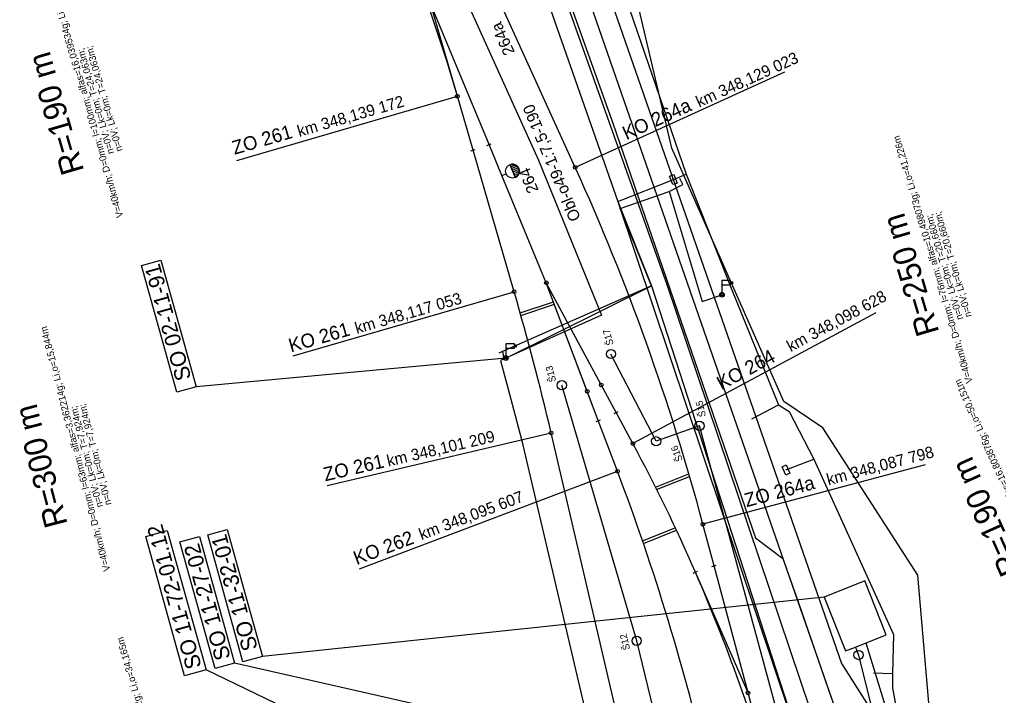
# Model space of a CAD drawing. Extents: x -820988 to -820703, y -1070846 to -1070074.
# Drawn here: x -820878.5 to -820772.1, y -1070418.8 to -1070345.4 of the extents above; entities that cross this region are included whole.
import ezdxf

# ---------------------------------------------------------------- set-up
doc = ezdxf.new("R2010")
doc.units = 0
for name, color, linetype in [('_PS_SO_číslo', 7, 'Continuous'), ('PS-11-02-31', 7, 'Continuous'), ('PS-11-02-41', 7, 'Continuous'), ('PS-11-02-91', 7, 'Continuous'), ('PS-11-02-92', 7, 'Continuous'), ('SO-11-10-01', 7, 'Continuous'), ('SO-11-31-01', 7, 'Continuous'), ('SO-11-32-01', 7, 'Continuous'), ('SO-11-50-01', 7, 'Continuous'), ('SO-11-79-01', 7, 'Continuous'), ('SO-11-86-01', 7, 'Continuous')]:
    doc.layers.add(name, color=color, linetype=linetype)

msp = doc.modelspace()

# ---------------------------------------------------------------- linework, layer by layer
at = {"layer": '_PS_SO_číslo'}
for p, q in [((-820825.63, -1070382.19), (-820859.3, -1070385.32)), ((-820791.02, -1070408.16), (-820852.1, -1070414.6)), ((-820809.59, -1070425.65), (-820855.13, -1070415.34)), ((-820805.22, -1070441.5), (-820858.23, -1070416.07))]:
    msp.add_line(p, q, dxfattribs=at)
for points in [[(-820863.13, -1070371.54), (-820859.3, -1070385.32), (-820861.42, -1070385.91), (-820865.25, -1070372.13)], [(-820855.93, -1070400.82), (-820852.1, -1070414.6), (-820854.22, -1070415.19), (-820858.05, -1070401.41)], [(-820862.45, -1070400.91), (-820858.23, -1070416.07), (-820860.57, -1070416.72), (-820864.78, -1070401.56)], [(-820858.96, -1070401.56), (-820855.13, -1070415.34), (-820857.25, -1070415.93), (-820861.08, -1070402.15)]]:
    msp.add_lwpolyline(points, close=True, dxfattribs=at)
at = {"layer": 'PS-11-02-31'}
msp.add_line((-820795.17, -1070394.35), (-820792.15, -1070393.19), dxfattribs=at)
for points in [[(-820959.28, -1070122.22), (-820934.84, -1070144.09), (-820933, -1070146.6), (-820925.15, -1070161.74), (-820918.63, -1070175.61), (-820911.37, -1070188.87), (-820902.58, -1070186.65), (-820896.69, -1070196.98), (-820870.46, -1070236.45), (-820846.57, -1070277.08), (-820842.6, -1070282.11), (-820813.47, -1070365.17), (-820809.8, -1070374.33), (-820792.8, -1070426.72), (-820792.34, -1070428.47), (-820790.08, -1070430.86), (-820788.92, -1070435.58), (-820780.39, -1070470.86), (-820770.55, -1070511.61), (-820767.89, -1070524.68), (-820765.3, -1070562.4), (-820759.61, -1070562.18)], [(-820834.74, -1070280.72), (-820830.77, -1070287.4), (-820826.6, -1070295.78), (-820822.74, -1070307.42), (-820822.4, -1070310.54), (-820820.82, -1070316.36), (-820815.08, -1070335.82), (-820806.04, -1070362.21), (-820801.05, -1070374.78), (-820795.98, -1070387.28), (-820794.84, -1070388), (-820792.15, -1070393.19), (-820783.48, -1070412.23), (-820783.6, -1070416.46), (-820783.6, -1070418.02), (-820782.43, -1070424.35)], [(-820813.21, -1070365.95), (-820807.86, -1070364.09), (-820806.37, -1070363.35), (-820806.71, -1070362.68)], [(-820825.63, -1070382.19), (-820809.8, -1070374.33)]]:
    msp.add_lwpolyline(points, dxfattribs=at)
for points in [[(-820807.37, -1070362.24), (-820806.99, -1070363.17), (-820807.46, -1070363.35), (-820807.83, -1070362.43)], [(-820795.2, -1070394.91), (-820795.6, -1070393.99), (-820795.14, -1070393.79), (-820794.74, -1070394.71)]]:
    msp.add_lwpolyline(points, close=True, dxfattribs=at)
at = {"layer": 'PS-11-02-41'}
for points in [[(-820882.99, -1070201.13), (-820875.54, -1070207.75), (-820872.79, -1070212.31), (-820866.57, -1070222.1), (-820863.69, -1070232.23), (-820854.15, -1070247.2), (-820844.78, -1070263.71), (-820834.74, -1070280.72), (-820830.77, -1070287.4), (-820826.6, -1070295.78), (-820822.74, -1070307.42), (-820822.4, -1070310.54), (-820820.82, -1070316.36), (-820815.08, -1070335.82), (-820806.04, -1070362.21), (-820801.05, -1070374.78), (-820795.98, -1070387.28), (-820794.84, -1070388), (-820792.15, -1070393.19), (-820783.48, -1070412.23), (-820783.6, -1070416.46), (-820783.6, -1070418.02), (-820782.43, -1070424.35)], [(-820813.47, -1070365.17), (-820807.41, -1070362.8), (-820806.04, -1070362.21)]]:
    msp.add_lwpolyline(points, dxfattribs=at)
at = {"layer": 'PS-11-02-91'}
for p, q in [((-820802.13, -1070374.23), (-820802.13, -1070375.06)), ((-820801, -1070373.89), (-820801.2, -1070374)), ((-820801, -1070374.12), (-820801.2, -1070374)), ((-820801, -1070373.89), (-820801, -1070374.12)), ((-820802.13, -1070375.31), (-820802.13, -1070375.31)), ((-820825.63, -1070381.11), (-820825.63, -1070381.94)), ((-820824.5, -1070380.77), (-820824.7, -1070380.88)), ((-820824.5, -1070381), (-820824.7, -1070380.88)), ((-820824.5, -1070380.77), (-820824.5, -1070381)), ((-820825.63, -1070382.19), (-820825.63, -1070382.19))]:
    msp.add_line(p, q, dxfattribs=at)
for points in [[(-820825.63, -1070382.19), (-820809.8, -1070374.33), (-820813.21, -1070365.95), (-820807.86, -1070364.09), (-820806.37, -1070363.35), (-820806.71, -1070362.68)], [(-820807.86, -1070364.09), (-820804.29, -1070376.06), (-820802.13, -1070375.31)]]:
    msp.add_lwpolyline(points, dxfattribs=at)
for points in [[(-820801.2, -1070373.77), (-820802.13, -1070373.77), (-820802.13, -1070374.23), (-820801.2, -1070374.23)], [(-820824.7, -1070380.65), (-820825.63, -1070380.65), (-820825.63, -1070381.11), (-820824.7, -1070381.11)]]:
    msp.add_lwpolyline(points, close=True, dxfattribs=at)
for centre, radius in [((-820802.13, -1070375.31), 0.25), ((-820802.13, -1070375.31), 0.125), ((-820825.63, -1070382.19), 0.25), ((-820825.63, -1070382.19), 0.125)]:
    msp.add_circle(centre, radius, dxfattribs=at)
at = {"layer": 'PS-11-02-92'}
for points in [[(-820882.99, -1070201.13), (-820875.54, -1070207.75), (-820872.79, -1070212.31), (-820866.57, -1070222.1), (-820863.69, -1070232.23), (-820854.15, -1070247.2), (-820844.78, -1070263.71), (-820834.74, -1070280.72), (-820830.77, -1070287.4), (-820826.6, -1070295.78), (-820822.74, -1070307.42), (-820822.4, -1070310.54), (-820820.82, -1070316.36), (-820815.08, -1070335.82), (-820806.04, -1070362.21), (-820801.05, -1070374.78), (-820795.98, -1070387.28), (-820794.84, -1070388), (-820792.15, -1070393.19), (-820783.48, -1070412.23), (-820783.6, -1070416.46), (-820783.6, -1070418.02), (-820782.43, -1070424.35)], [(-820813.47, -1070365.17), (-820807.41, -1070362.8), (-820806.04, -1070362.21)]]:
    msp.add_lwpolyline(points, dxfattribs=at)
at = {"layer": 'SO-11-10-01'}
for p, q in [((-820818.09, -1070361.48), (-820834.6, -1070325.15)), ((-820795.33, -1070351.14), (-820818.09, -1070361.48)), ((-820854.9, -1070360.72), (-820830.9, -1070353.75)), ((-820827.69, -1070359.09), (-820827.23, -1070358.9)), ((-820826.07, -1070362.36), (-820827.46, -1070358.99)), ((-820829.44, -1070359.67), (-820828.96, -1070359.53)), ((-820824.73, -1070374.99), (-820829.2, -1070359.6)), ((-820825.2, -1070361.18), (-820824.63, -1070362.57)), ((-820824.18, -1070361.74), (-820825.13, -1070361.34)), ((-820824.28, -1070361.48), (-820825.08, -1070361.15)), ((-820826.07, -1070362.36), (-820825.61, -1070362.16)), ((-820824.17, -1070361.96), (-820825.03, -1070361.6)), ((-820824.22, -1070362.15), (-820824.92, -1070361.86)), ((-820824.32, -1070362.33), (-820824.81, -1070362.13)), ((-820824.47, -1070362.48), (-820824.7, -1070362.39)), ((-820848.74, -1070381.94), (-820824.73, -1070374.99)), ((-820824.08, -1070377.26), (-820820.45, -1070376.07)), ((-820824, -1070377.55), (-820820.35, -1070376.35)), ((-820822.23, -1070376.81), (-820822.23, -1070376.81)), ((-820785.41, -1070377.26), (-820811.82, -1070391.48)), ((-820813.87, -1070388.22), (-820813.42, -1070387.98)), ((-820811.82, -1070391.48), (-820813.65, -1070388.1)), ((-820815.81, -1070389.07), (-820815.34, -1070388.89)), ((-820813.49, -1070394.48), (-820815.58, -1070388.98)), ((-820845.05, -1070396.03), (-820820.71, -1070390.32)), ((-820841.56, -1070405.09), (-820813.49, -1070394.48)), ((-820780.05, -1070393.78), (-820804.2, -1070400.24)), ((-820809.37, -1070396.2), (-820805.73, -1070394.78)), ((-820809.24, -1070396.47), (-820805.65, -1070395.07)), ((-820807.51, -1070395.64), (-820807.51, -1070395.64)), ((-820810.77, -1070402.05), (-820807.22, -1070400.62)), ((-820810.67, -1070402.34), (-820807.09, -1070400.89)), ((-820802.99, -1070404.76), (-820804.2, -1070400.24)), ((-820808.93, -1070401.47), (-820808.93, -1070401.47)), ((-820803.23, -1070404.82), (-820802.75, -1070404.69)), ((-820799.29, -1070418.58), (-820802.99, -1070404.76)), ((-820805.25, -1070405.57), (-820804.79, -1070405.36)), ((-820799.29, -1070418.58), (-820805.02, -1070405.47)), ((-820799.29, -1070418.58), (-820805.02, -1070405.47)), ((-820795.8, -1070431.62), (-820799.29, -1070418.58))]:
    msp.add_line(p, q, dxfattribs=at)
for points in [[(-820827.46, -1070358.99), (-820833.83, -1070343.65), (-820837.56, -1070334.67)], [(-820827.46, -1070358.99), (-820833.83, -1070343.65), (-820837.56, -1070334.67)], [(-820829.2, -1070359.6), (-820830.9, -1070353.75), (-820833.83, -1070343.65)], [(-820829.2, -1070359.6), (-820830.9, -1070353.75), (-820833.83, -1070343.65)], [(-820815.58, -1070388.98), (-820821.23, -1070374), (-820826.07, -1070362.36)], [(-820815.58, -1070388.98), (-820816.78, -1070385.8), (-820821.23, -1070374), (-820826.07, -1070362.36)], [(-820813.65, -1070388.1), (-820815.26, -1070385.11), (-820821.23, -1070374)], [(-820813.65, -1070388.1), (-820815.26, -1070385.11), (-820821.23, -1070374)], [(-820791.84, -1070436.4), (-820804.58, -1070389.55), (-820809.29, -1070391.23), (-820814.2, -1070381.75)], [(-820804.91, -1070439.6), (-820811.4, -1070412.91), (-820819.54, -1070385.14)], [(-820761.02, -1070645.41), (-820786.89, -1070534.87), (-820787.46, -1070532.43), (-820788.03, -1070530), (-820808.59, -1070442.09), (-820809.13, -1070439.8), (-820809.67, -1070437.51), (-820820.71, -1070390.32)], [(-820795.59, -1070432.4), (-820799.29, -1070418.58), (-820802.99, -1070404.76)]]:
    msp.add_lwpolyline(points, dxfattribs=at)
for centre, radius in [((-820830.9, -1070353.75), 0.2), ((-820824.91, -1070361.88), 0.75), ((-820818.09, -1070361.48), 0.2), ((-820821.23, -1070374), 0.2), ((-820824.73, -1070374.99), 0.2), ((-820814.2, -1070381.75), 0.5), ((-820819.54, -1070385.14), 0.5), ((-820815.26, -1070385.11), 0.2), ((-820816.78, -1070385.8), 0.2), ((-820804.58, -1070389.55), 0.5), ((-820820.71, -1070390.32), 0.2), ((-820811.82, -1070391.48), 0.2), ((-820809.29, -1070391.23), 0.5), ((-820813.49, -1070394.48), 0.2), ((-820804.2, -1070400.24), 0.2), ((-820811.4, -1070412.91), 0.5), ((-820799.29, -1070418.58), 0.2)]:
    msp.add_circle(centre, radius, dxfattribs=at)
msp.add_arc((-820824.91, -1070361.88), 0.75, 292.5346, 112.5346, dxfattribs=at)
for centre, major_axis, ratio, start_param, end_param in [((-821013.36, -1070406.73), (42.75, 185.13), 0.999991, 5.221901, 5.328341), ((-821045.68, -1070464.9), (-139.53, 207.44), 0.999954, 4.381904, 4.546806), ((-821102.72, -1070456.2), (-73.52, 290.85), 0.96534, 4.694931, 4.747744), ((-820979.11, -1070481.53), (-110.75, 154.39), 0.9999, 4.502101, 4.583959), ((-821056.7, -1070486.4), (38.3, 257.16), 0.999985, 5.090175, 5.221577), ((-820979.11, -1070481.56), (-128.26, 140.17), 0.999982, 4.237298, 4.383398)]:
    msp.add_ellipse(centre, major_axis=major_axis, ratio=ratio, start_param=start_param, end_param=end_param, dxfattribs=at)
at = {"layer": 'SO-11-31-01'}
msp.add_line((-820786.49, -1070413.14), (-820781.3, -1070430.05), dxfattribs=at)
for points in [[(-820926.07, -1070123.29), (-820916.95, -1070167.12), (-820908.61, -1070171.6), (-820902.99, -1070184.31), (-820895.92, -1070196.33), (-820868.5, -1070237.37), (-820845.66, -1070276.46), (-820841.66, -1070281.51), (-820839.82, -1070285.2), (-820808.13, -1070374.18), (-820790.33, -1070426.97), (-820782.93, -1070433.41), (-820769.19, -1070488.5), (-820779.89, -1070491.4)], [(-820832.57, -1070337.97), (-820821.56, -1070335.44), (-820813.99, -1070356.68), (-820798.47, -1070401.74), (-820795.5, -1070403.96), (-820793.85, -1070408.69), (-820790.57, -1070418.13), (-820788.93, -1070422.85), (-820783.27, -1070428.36), (-820780.97, -1070427.76), (-820780.24, -1070428.17), (-820779.88, -1070429.72), (-820781.01, -1070429.99)]]:
    msp.add_lwpolyline(points, dxfattribs=at)
at = {"layer": 'SO-11-32-01'}
msp.add_lwpolyline([(-820788.7, -1070414.01), (-820787.62, -1070413.59), (-820784.28, -1070412.27), (-820786.6, -1070406.41), (-820791.02, -1070408.16)], close=True, dxfattribs=at)
msp.add_lwpolyline([(-820787.62, -1070413.59), (-820787.28, -1070414.46), (-820762.46, -1070514.35), (-820773.88, -1070517.14)], dxfattribs=at)
msp.add_circle((-820787.28, -1070414.46), 0.5, dxfattribs=at)
at = {"layer": 'SO-11-50-01'}
for points in [[(-820831.74, -1070299.72), (-820794.49, -1070406.87), (-820788.19, -1070424.98)], [(-820815.77, -1070338.8), (-820798.17, -1070389.42), (-820789.14, -1070415.39), (-820782.76, -1070425.41), (-820778.11, -1070440.81), (-820778.3, -1070451.36), (-820766.96, -1070499.85)]]:
    msp.add_lwpolyline(points, dxfattribs=at)
at = {"layer": 'SO-11-79-01'}
for points in [[(-820832.86, -1070278.44), (-820856.81, -1070291.29), (-820851.46, -1070300.37), (-820846.11, -1070309.46), (-820839.3, -1070322.5), (-820836.66, -1070328.49), (-820822.07, -1070360.7), (-820815.22, -1070377.53), (-820826.2, -1070382.45), (-820824.95, -1070387.21), (-820823.93, -1070391.03), (-820782.06, -1070569.19)], [(-820761.04, -1070511.48), (-820774.1, -1070459), (-820777.68, -1070442.4), (-820780.82, -1070405.78), (-820791.18, -1070389.77), (-820795.41, -1070386.91), (-820807.6, -1070359.39), (-820815.49, -1070325.84), (-820825.29, -1070295.05), (-820830.46, -1070283.22), (-820832.86, -1070278.44)]]:
    msp.add_lwpolyline(points, dxfattribs=at)
at = {"layer": 'SO-11-86-01'}
for p, q in [((-820826.01, -1070381.49), (-820825.87, -1070382.08)), ((-820798.87, -1070388.79), (-820795.98, -1070387.28)), ((-820795.17, -1070394.35), (-820792.15, -1070393.19)), ((-820785.65, -1070416.39), (-820783.6, -1070416.46))]:
    msp.add_line(p, q, dxfattribs=at)
for points in [[(-820870.46, -1070236.45), (-820846.57, -1070277.08), (-820842.6, -1070282.11), (-820813.47, -1070365.17), (-820792.8, -1070426.72), (-820792.34, -1070428.47), (-820790.08, -1070430.86), (-820788.92, -1070435.58), (-820780.39, -1070470.86), (-820770.55, -1070511.61), (-820767.89, -1070524.68), (-820765.3, -1070562.4), (-820759.61, -1070562.18), (-820765.13, -1070563.53), (-820782.39, -1070567.76), (-820781.93, -1070569.72), (-820782.39, -1070567.76)], [(-820844.78, -1070263.71), (-820834.74, -1070280.72), (-820830.77, -1070287.4), (-820826.6, -1070295.78), (-820822.74, -1070307.42), (-820822.4, -1070310.54), (-820820.82, -1070316.36), (-820815.08, -1070335.82), (-820806.04, -1070362.21), (-820801.05, -1070374.78), (-820795.98, -1070387.28), (-820794.84, -1070388), (-820792.15, -1070393.19), (-820783.48, -1070412.23), (-820783.6, -1070416.46), (-820783.6, -1070418.02), (-820782.43, -1070424.35), (-820780.96, -1070434.38), (-820773.91, -1070463.73), (-820769.35, -1070482.63)], [(-820813.47, -1070365.17), (-820807.41, -1070362.8), (-820806.04, -1070362.21)], [(-820809.8, -1070374.33), (-820826.01, -1070381.49), (-820826.39, -1070381.66)]]:
    msp.add_lwpolyline(points, dxfattribs=at)
for points in [[(-820807.37, -1070362.24), (-820806.99, -1070363.17), (-820807.46, -1070363.35), (-820807.83, -1070362.43)], [(-820795.2, -1070394.91), (-820795.6, -1070393.99), (-820795.14, -1070393.79), (-820794.74, -1070394.71)]]:
    msp.add_lwpolyline(points, close=True, dxfattribs=at)

# ---------------------------------------------------------------- texts
at = {"layer": '_PS_SO_číslo'}
for s, p in [('SO 02-11-91', (-820859.82, -1070384.37)), ('SO 11-72-01.12', (-820858.7, -1070415.7)), ('SO 11-32-01', (-820852.59, -1070413.73)), ('SO 11-27-02', (-820855.54, -1070414.75))]:
    msp.add_text(s, height=1.7, rotation=105.5289, dxfattribs=at).set_placement(p)
at = {"layer": 'SO-11-10-01'}
for s, height, rotation, p in [('V=40km/h; D=0mm; l=100mm; alfas=16,039534g; Li,o=47,87m', 0.75, 106.1938, (-820867.23, -1070366.81)), ('264a', 1.25, 114.438, (-820824.64, -1070348.95)), ('n=0V; Lk=0m; T=24,063m;', 0.75, 106.1938, (-820868.23, -1070359.9)), ('n=0V; Lk=0m; T=24,063m;', 0.75, 106.1938, (-820867.29, -1070359.63)), ('R=190 m', 2.5, 106.1938, (-820871.47, -1070361.84)), ('km 348,129 023', 1.25, 24.4385, (-820804.61, -1070354.98)), ('km 348,139 172', 1.25, 16.1921, (-820848.1, -1070358.17)), ('Obl-o49-1:7,5-190', 1.25, 112.5346, (-820817.47, -1070367.02)), ('KO 264a ', 1.5, 24.4385, (-820812.52, -1070358.53)), ('ZO 261 ', 1.5, 16.1921, (-820855.15, -1070360.11)), ('V=40km/h; D=0mm; l=76mm; alfas=10,498073g; Li,o=41,226m', 0.75, 106.528, (-820774.87, -1070384.81)), ('264', 1.25, 112.5346, (-820822.05, -1070363.96)), ('R=250 m', 2.5, 106.528, (-820778.49, -1070379.36)), ('n=0V; Lk=0m; T=20,660m;', 0.75, 106.528, (-820775.9, -1070377.91)), ('n=0V; Lk=0m; T=20,660m;', 0.75, 106.528, (-820774.97, -1070377.63)), ('km 348,117 053', 1.25, 16.1416, (-820841.84, -1070379.57)), ('km 348,098 628', 1.25, 28.2952, (-820794.66, -1070381.55)), ('KO 261 ', 1.5, 16.1416, (-820849, -1070381.59)), ('V=40km/h; D=0mm; l=63mm; alfas=3,362214g; Li,o=15,844m', 0.75, 104.5752, (-820868.64, -1070405.25)), ('Š17', 0.75, 104.5752, (-820813.92, -1070380.71)), ('KO 264 ', 1.5, 28.2952, (-820802.18, -1070385.71)), ('Š13', 0.75, 104.5752, (-820820.16, -1070384.69)), ('V=40km/h; D=0mm; l=100mm; alfas=16,803876g; Li,o=50,151m', 0.75, 114.1933, (-820764.49, -1070410.46)), ('Š15', 0.75, 103.1701, (-820803.87, -1070388.49)), ('R=300 m', 2.5, 104.5752, (-820873.27, -1070400.23)), ('n=0V; Lk=0m; T=7,924m;', 0.75, 104.5752, (-820869.44, -1070398.31)), ('n=0V; Lk=0m; T=7,924m;', 0.75, 104.5752, (-820868.5, -1070398.07)), ('km 348,101 209', 1.25, 13.2204, (-820838.41, -1070393.99)), ('Š16', 0.75, 110.7019, (-820806.38, -1070393.28)), ('km 348,087 798', 1.25, 14.9906, (-820790.56, -1070396.03)), ('ZO 261 ', 1.5, 13.2204, (-820845.28, -1070395.59)), ('R=190 m', 2.5, 114.1933, (-820769.43, -1070405.18)), ('ZO 264a ', 1.5, 14.9906, (-820799.46, -1070398.4)), ('km 348,095 607', 1.25, 20.702, (-820834.8, -1070401.98)), ('KO 262 ', 1.5, 20.702, (-820841.86, -1070404.7)), ('V=40km/h; D=0mm; l=73mm; alfas=8,365382g; Li,o=34,165m', 0.75, 105.6858, (-820859.82, -1070438.86)), ('Š12', 0.75, 103.1701, (-820812.12, -1070413.82))]:
    msp.add_text(s, height=height, rotation=rotation, dxfattribs=at).set_placement(p)

doc.saveas('drawing.dxf')
